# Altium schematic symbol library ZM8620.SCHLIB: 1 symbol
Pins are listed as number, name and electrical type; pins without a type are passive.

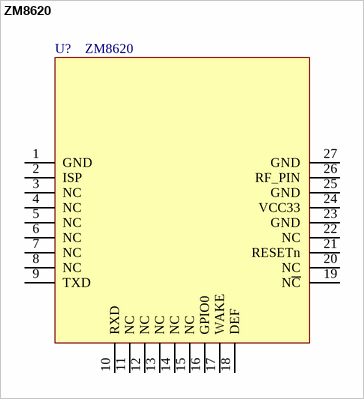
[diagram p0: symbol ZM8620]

## ZM8620
designator U?
名称: ZigBee模块; 厂商: ZHIYUAN; 贴片和直插: SMT; PCB备注: yyj210419; 生产单位: PCS
footprint AW5161P2-MG21_RevA (ZLGLIB)
pins: 1 GND, 2 ISP, 3 NC, 4 NC, 5 NC, 6 NC, 7 NC, 8 NC, 9 TXD, 10 RXD, 11 NC, 12 NC, 13 NC, 14 NC, 15 NC, 16 GPIO0, 17 WAKE, 18 DEF, 19 N~{C}, 20 NC, 21 RESETn, 22 NC, 23 GND, 24 VCC33, 25 GND, 26 RF_PIN, 27 GND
